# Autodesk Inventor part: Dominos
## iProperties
Author: FlavienM
Shininess: 20.0
Angle Display Precision: 2
Document Length Units: 11269
Document Angle Units: 11283
Document Time Units: 11279
Document Mass Units: 11290
Document Length Units Precision: 3
Document Angle Units Precision: 2
Compacted: True
PropertySet Name: _Private Model Information
Created: 2002-06
Part Number: Dominos
Material: Par défaut
Document SubType Name: Modélisation
Designer: FlavienM
Control State: 0
Master: False
Checked Out: False
PropertySet Name: Design Tracking Control
Density: 0.0
Volumn: 0.0
Area: 0.0
PropertySet Name: Model Information
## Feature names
1. Extrusion1
2. Extrusion2
3. Symétrie1 [Mirror]
